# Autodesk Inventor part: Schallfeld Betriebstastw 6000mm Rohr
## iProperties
Shininess: 20.0
Length Units: 11269
Angle Units: 11279
Time Units: 11290
Mass Units: 11283
Length Display Precision: 2
Angle Display Precision: 2
Category: Schallfelder
Part Number: Schallfeld Betriebstastw 6000mm Rohr
Material: Lexan (klar)
Document SubType Name: Modellieren
Checked By: Alves
Created: 2005-08
Designer: Grube
Manufacturer: Standard
Standards Organization: Custom
Description: Schallfeld 6,0m
Density: 0.0
Volumn: 0.0
Area: 0.0
PropertySet Name: Model Information
Control State: 0
Master: False
Checked Out: False
Last Check In By: Kramp
Last Check In Date: 2005-08-11
ME: ST
Comments: keine Bemerkung
Title: Schallfelder
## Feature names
1. Innenglocke [Revolution]
